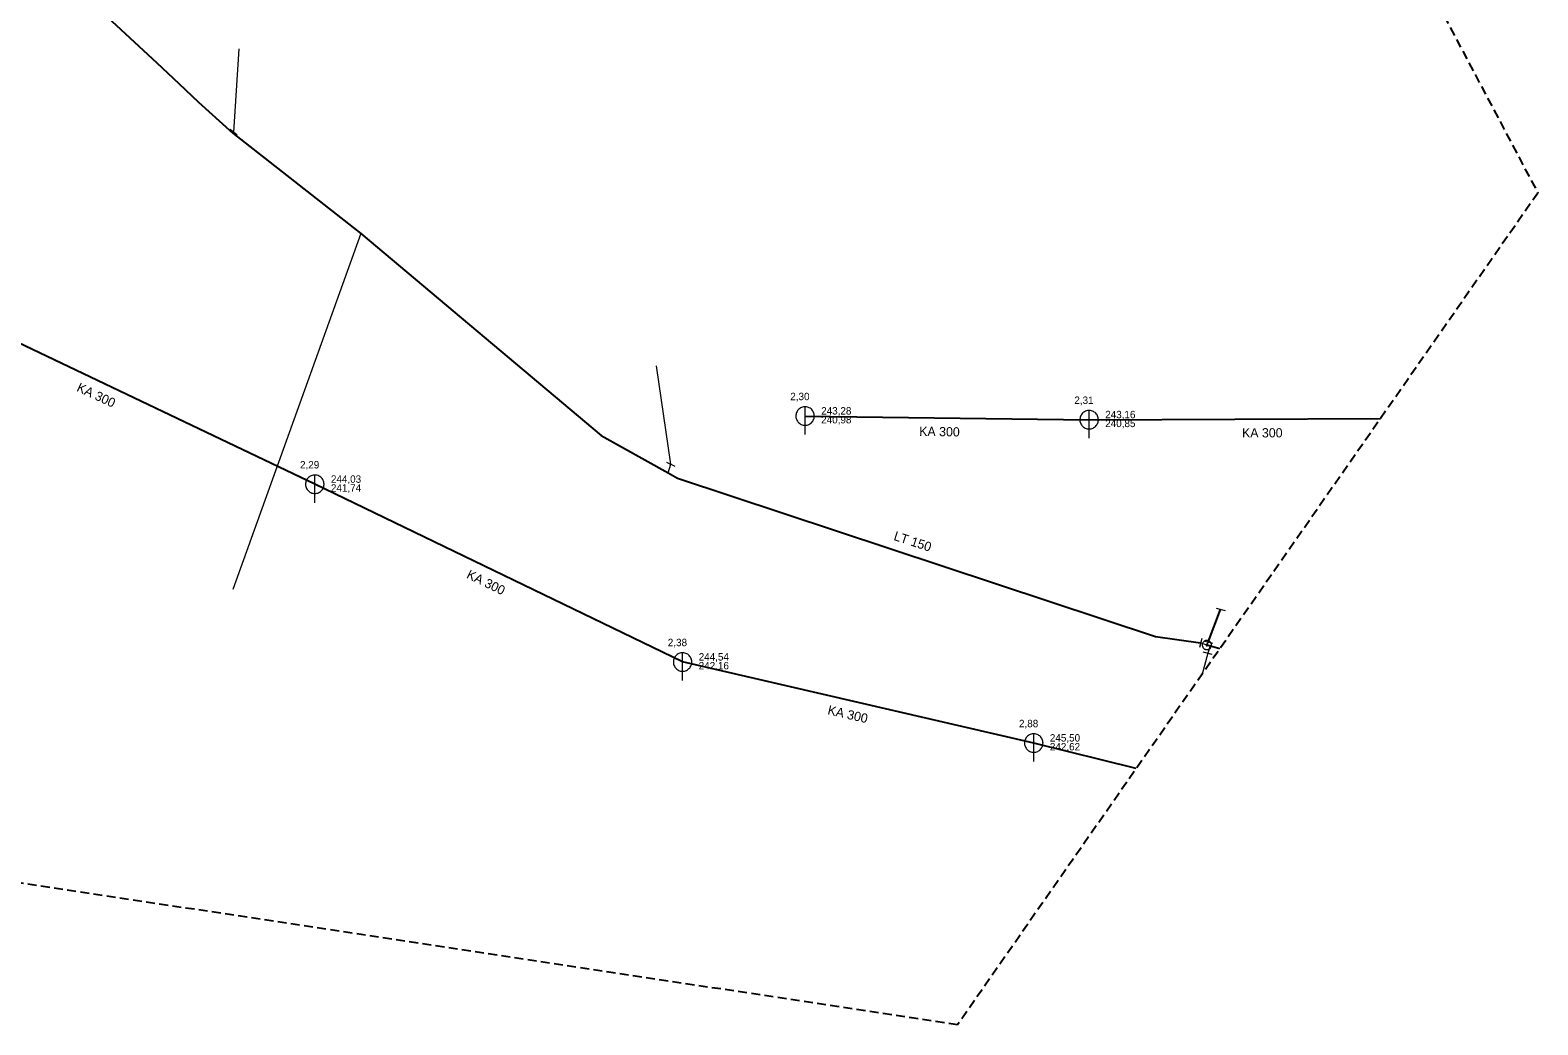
# Model space of a CAD drawing. Extents: x -777996 to -777727, y -976581 to -976199.
# Drawn here: x -777889.9 to -777726.8, y -976581.2 to -976473.6 of the extents above; entities that cross this region are included whole.
import ezdxf

# ---------------------------------------------------------------- set-up
doc = ezdxf.new("R2010")
doc.units = 0
doc.header["$LTSCALE"] = 0.32
doc.linetypes.add('MEDIUM_DASHED', pattern=[4.5, 3, -1.5])
for name, color, linetype, lineweight in [('1', 7, 'MEDIUM_DASHED', 25), ('13', 7, 'Continuous', 13), ('14', 7, 'Continuous', 25), ('17', 7, 'Continuous', 25), ('22', 7, 'Continuous', 13), ('34', 7, 'Continuous', 13), ('47', 7, 'Continuous', 13)]:
    doc.layers.add(name, color=color, linetype=linetype, lineweight=lineweight)

msp = doc.modelspace()

# ---------------------------------------------------------------- linework, layer by layer
at = {"layer": '1'}
msp.add_lwpolyline([(-777995.417, -976203.033), (-777848.18, -976198.846), (-777864.927, -976230.247), (-777726.762, -976491.225), (-777789.565, -976581.242), (-777941.686, -976558.215), (-777989.136, -976405.396)], close=True, dxfattribs=at)
at = {"layer": '13'}
for p, q in [((-777867.889, -976484.627), (-777867.309, -976475.629)), ((-777867.989, -976484.745), (-777867.889, -976484.627)), ((-777854.131, -976495.614), (-777868.002, -976534.129)), ((-777820.6, -976520.57), (-777822.127, -976509.92)), ((-777762.489, -976541.039), (-777763.1, -976543.309))]:
    msp.add_line(p, q, dxfattribs=at)
at = {"layer": '14'}
for p, q in [((-777859.114, -976522.743), (-777903.695, -976501.491)), ((-777806.059, -976515.357), (-777775.322, -976515.76)), ((-777775.322, -976515.76), (-777743.786, -976515.626)), ((-777819.315, -976541.977), (-777859.114, -976522.743)), ((-777781.311, -976550.747), (-777819.315, -976541.977)), ((-777770.223, -976553.518), (-777781.311, -976550.747))]:
    msp.add_line(p, q, dxfattribs=at)
at = {"layer": '14', "lineweight": 13}
for p, q in [((-777820.87, -976521.516), (-777820.6, -976520.57)), ((-777762.581, -976540.14), (-777763.26, -976539.92)), ((-777762.581, -976540.14), (-777762.44, -976539.829)), ((-777762.214, -976540.243), (-777762.489, -976541.039))]:
    msp.add_line(p, q, dxfattribs=at)
at = {"layer": '17'}
msp.add_line((-777762.44, -976539.829), (-777761.095, -976536.292), dxfattribs=at)
for points in [[(-777885.941, -976468.086), (-777876.204, -976477.129), (-777873.846, -976479.364), (-777871.717, -976481.385), (-777867.989, -976484.745), (-777854.131, -976495.614), (-777828.123, -976517.456), (-777820.88, -976521.51), (-777819.881, -976522.07), (-777768.129, -976539.208), (-777763.26, -976539.92)], [(-777761.165, -976540.537), (-777762.203, -976540.246), (-777762.581, -976540.14)]]:
    msp.add_lwpolyline(points, dxfattribs=at)
at = {"layer": '22'}
for p, q in [((-777806.059, -976517.357), (-777806.058, -976514.357)), ((-777775.323, -976517.76), (-777775.322, -976514.76)), ((-777859.115, -976524.744), (-777859.114, -976521.744)), ((-777819.315, -976543.977), (-777819.314, -976540.977)), ((-777781.312, -976552.747), (-777781.311, -976549.747))]:
    msp.add_line(p, q, dxfattribs=at)
for points in [[(-777805.059, -976515.357), (-777805.064, -976515.248), (-777805.082, -976515.14), (-777805.112, -976515.034), (-777805.152, -976514.933), (-777805.204, -976514.836), (-777805.266, -976514.746), (-777805.338, -976514.663), (-777805.418, -976514.589), (-777805.506, -976514.523), (-777805.6, -976514.468), (-777805.7, -976514.423), (-777805.805, -976514.39), (-777805.912, -976514.368), (-777806.021, -976514.358), (-777806.131, -976514.36), (-777806.239, -976514.374), (-777806.346, -976514.399), (-777806.449, -976514.436), (-777806.547, -976514.485), (-777806.639, -976514.543), (-777806.725, -976514.612), (-777806.802, -976514.689), (-777806.871, -976514.775), (-777806.93, -976514.867), (-777806.978, -976514.965), (-777807.015, -976515.068), (-777807.041, -976515.175), (-777807.055, -976515.283), (-777807.058, -976515.393), (-777807.048, -976515.502), (-777807.027, -976515.609), (-777806.993, -976515.713), (-777806.949, -976515.813), (-777806.894, -976515.908), (-777806.828, -976515.996), (-777806.754, -976516.076), (-777806.671, -976516.148), (-777806.581, -976516.21), (-777806.485, -976516.262), (-777806.383, -976516.303), (-777806.278, -976516.333), (-777806.17, -976516.351), (-777806.06, -976516.357), (-777805.951, -976516.351), (-777805.843, -976516.333), (-777805.738, -976516.304), (-777805.636, -976516.263), (-777805.539, -976516.211), (-777805.449, -976516.149), (-777805.366, -976516.078), (-777805.291, -976515.998), (-777805.226, -976515.91), (-777805.17, -976515.816), (-777805.126, -976515.716), (-777805.092, -976515.612), (-777805.07, -976515.504), (-777805.06, -976515.395)], [(-777774.323, -976515.76), (-777774.328, -976515.651), (-777774.346, -976515.543), (-777774.376, -976515.437), (-777774.416, -976515.336), (-777774.468, -976515.239), (-777774.53, -976515.149), (-777774.602, -976515.066), (-777774.682, -976514.992), (-777774.77, -976514.926), (-777774.864, -976514.871), (-777774.964, -976514.826), (-777775.069, -976514.793), (-777775.176, -976514.771), (-777775.285, -976514.761), (-777775.395, -976514.763), (-777775.503, -976514.777), (-777775.61, -976514.802), (-777775.713, -976514.839), (-777775.811, -976514.888), (-777775.903, -976514.946), (-777775.989, -976515.015), (-777776.066, -976515.092), (-777776.135, -976515.178), (-777776.194, -976515.27), (-777776.242, -976515.368), (-777776.279, -976515.471), (-777776.305, -976515.578), (-777776.319, -976515.686), (-777776.322, -976515.796), (-777776.312, -976515.905), (-777776.291, -976516.012), (-777776.257, -976516.116), (-777776.213, -976516.216), (-777776.158, -976516.311), (-777776.092, -976516.399), (-777776.018, -976516.479), (-777775.935, -976516.551), (-777775.845, -976516.613), (-777775.749, -976516.665), (-777775.647, -976516.706), (-777775.542, -976516.736), (-777775.434, -976516.754), (-777775.324, -976516.76), (-777775.215, -976516.754), (-777775.107, -976516.736), (-777775.002, -976516.707), (-777774.9, -976516.666), (-777774.803, -976516.614), (-777774.713, -976516.552), (-777774.63, -976516.481), (-777774.555, -976516.401), (-777774.49, -976516.313), (-777774.434, -976516.219), (-777774.39, -976516.119), (-777774.356, -976516.015), (-777774.334, -976515.907), (-777774.324, -976515.798)], [(-777858.115, -976522.744), (-777858.12, -976522.635), (-777858.138, -976522.527), (-777858.168, -976522.421), (-777858.208, -976522.32), (-777858.26, -976522.223), (-777858.322, -976522.133), (-777858.394, -976522.05), (-777858.474, -976521.976), (-777858.562, -976521.91), (-777858.656, -976521.855), (-777858.756, -976521.81), (-777858.861, -976521.777), (-777858.968, -976521.755), (-777859.077, -976521.745), (-777859.187, -976521.747), (-777859.295, -976521.761), (-777859.402, -976521.786), (-777859.505, -976521.823), (-777859.603, -976521.872), (-777859.695, -976521.93), (-777859.781, -976521.999), (-777859.858, -976522.076), (-777859.927, -976522.162), (-777859.986, -976522.254), (-777860.034, -976522.352), (-777860.071, -976522.455), (-777860.097, -976522.562), (-777860.111, -976522.67), (-777860.114, -976522.78), (-777860.104, -976522.889), (-777860.083, -976522.996), (-777860.049, -976523.1), (-777860.005, -976523.2), (-777859.95, -976523.295), (-777859.884, -976523.383), (-777859.81, -976523.463), (-777859.727, -976523.535), (-777859.637, -976523.597), (-777859.541, -976523.649), (-777859.439, -976523.69), (-777859.334, -976523.72), (-777859.226, -976523.738), (-777859.116, -976523.744), (-777859.007, -976523.738), (-777858.899, -976523.72), (-777858.794, -976523.691), (-777858.692, -976523.65), (-777858.595, -976523.598), (-777858.505, -976523.536), (-777858.422, -976523.465), (-777858.347, -976523.385), (-777858.282, -976523.297), (-777858.226, -976523.203), (-777858.182, -976523.103), (-777858.148, -976522.999), (-777858.126, -976522.891), (-777858.116, -976522.782)], [(-777818.315, -976541.977), (-777818.32, -976541.868), (-777818.338, -976541.76), (-777818.368, -976541.654), (-777818.408, -976541.553), (-777818.46, -976541.456), (-777818.522, -976541.366), (-777818.594, -976541.283), (-777818.674, -976541.209), (-777818.762, -976541.143), (-777818.856, -976541.088), (-777818.956, -976541.043), (-777819.061, -976541.01), (-777819.168, -976540.988), (-777819.277, -976540.978), (-777819.387, -976540.98), (-777819.495, -976540.994), (-777819.602, -976541.019), (-777819.705, -976541.056), (-777819.803, -976541.105), (-777819.895, -976541.163), (-777819.981, -976541.232), (-777820.058, -976541.309), (-777820.127, -976541.395), (-777820.186, -976541.487), (-777820.234, -976541.585), (-777820.271, -976541.688), (-777820.297, -976541.795), (-777820.311, -976541.903), (-777820.314, -976542.013), (-777820.304, -976542.122), (-777820.283, -976542.229), (-777820.249, -976542.333), (-777820.205, -976542.433), (-777820.15, -976542.528), (-777820.084, -976542.616), (-777820.01, -976542.696), (-777819.927, -976542.768), (-777819.837, -976542.83), (-777819.741, -976542.882), (-777819.639, -976542.923), (-777819.534, -976542.953), (-777819.426, -976542.971), (-777819.316, -976542.977), (-777819.207, -976542.971), (-777819.099, -976542.953), (-777818.994, -976542.924), (-777818.892, -976542.883), (-777818.795, -976542.831), (-777818.705, -976542.769), (-777818.622, -976542.698), (-777818.547, -976542.618), (-777818.482, -976542.53), (-777818.426, -976542.436), (-777818.382, -976542.336), (-777818.348, -976542.232), (-777818.326, -976542.124), (-777818.316, -976542.015)], [(-777780.312, -976550.747), (-777780.317, -976550.638), (-777780.335, -976550.53), (-777780.365, -976550.424), (-777780.405, -976550.323), (-777780.457, -976550.226), (-777780.519, -976550.136), (-777780.591, -976550.053), (-777780.671, -976549.979), (-777780.759, -976549.913), (-777780.853, -976549.858), (-777780.953, -976549.813), (-777781.058, -976549.78), (-777781.165, -976549.758), (-777781.274, -976549.748), (-777781.384, -976549.75), (-777781.492, -976549.764), (-777781.599, -976549.789), (-777781.702, -976549.826), (-777781.8, -976549.875), (-777781.892, -976549.933), (-777781.978, -976550.002), (-777782.055, -976550.079), (-777782.124, -976550.165), (-777782.183, -976550.257), (-777782.231, -976550.355), (-777782.268, -976550.458), (-777782.294, -976550.565), (-777782.308, -976550.673), (-777782.311, -976550.783), (-777782.301, -976550.892), (-777782.28, -976550.999), (-777782.246, -976551.103), (-777782.202, -976551.203), (-777782.147, -976551.298), (-777782.081, -976551.386), (-777782.007, -976551.466), (-777781.924, -976551.538), (-777781.834, -976551.6), (-777781.738, -976551.652), (-777781.636, -976551.693), (-777781.531, -976551.723), (-777781.423, -976551.741), (-777781.313, -976551.747), (-777781.204, -976551.741), (-777781.096, -976551.723), (-777780.991, -976551.694), (-777780.889, -976551.653), (-777780.792, -976551.601), (-777780.702, -976551.539), (-777780.619, -976551.468), (-777780.544, -976551.388), (-777780.479, -976551.3), (-777780.423, -976551.206), (-777780.379, -976551.106), (-777780.345, -976551.002), (-777780.323, -976550.894), (-777780.313, -976550.785)]]:
    msp.add_lwpolyline(points, close=True, dxfattribs=at)
at = {"layer": '34'}
for p, q in [((-777868.272, -976484.306), (-777867.506, -976484.948)), ((-777821.049, -976520.351), (-777820.15, -976520.789)), ((-777761.579, -976536.167), (-777760.61, -976536.417)), ((-777763.134, -976539.435), (-777763.384, -976540.404)), ((-777762.006, -976541.168), (-777762.971, -976540.908)), ((-777762.924, -976539.704), (-777761.955, -976539.954))]:
    msp.add_line(p, q, dxfattribs=at)
at = {"layer": '47'}
for points in [[(-777762.089, -976540.233), (-777762.083, -976540.181), (-777762.081, -976540.129), (-777762.085, -976540.077), (-777762.094, -976540.025), (-777762.108, -976539.975), (-777762.129, -976539.926), (-777762.154, -976539.881), (-777762.183, -976539.837), (-777762.216, -976539.797), (-777762.254, -976539.761), (-777762.296, -976539.728), (-777762.341, -976539.702), (-777762.387, -976539.678), (-777762.437, -976539.661), (-777762.487, -976539.648), (-777762.539, -976539.642), (-777762.591, -976539.64), (-777762.644, -976539.644), (-777762.695, -976539.653), (-777762.745, -976539.667), (-777762.794, -976539.688), (-777762.84, -976539.713), (-777762.884, -976539.742), (-777762.924, -976539.775), (-777762.959, -976539.813), (-777762.992, -976539.855), (-777763.019, -976539.899), (-777763.042, -976539.946), (-777763.059, -976539.996), (-777763.072, -976540.046), (-777763.078, -976540.098), (-777763.08, -976540.15), (-777763.077, -976540.203), (-777763.067, -976540.254), (-777763.053, -976540.304), (-777763.033, -976540.353), (-777763.008, -976540.399), (-777762.979, -976540.442), (-777762.945, -976540.483), (-777762.907, -976540.518), (-777762.865, -976540.551), (-777762.822, -976540.578), (-777762.774, -976540.601), (-777762.724, -976540.618), (-777762.674, -976540.631), (-777762.622, -976540.637), (-777762.57, -976540.639), (-777762.518, -976540.636), (-777762.466, -976540.626), (-777762.416, -976540.612), (-777762.367, -976540.592), (-777762.322, -976540.567), (-777762.278, -976540.538), (-777762.238, -976540.504), (-777762.202, -976540.466), (-777762.169, -976540.424), (-777762.143, -976540.38), (-777762.119, -976540.333), (-777762.102, -976540.283)], [(-777762.5, -976540.155), (-777762.498, -976540.146), (-777762.499, -976540.138), (-777762.499, -976540.129), (-777762.501, -976540.121), (-777762.503, -976540.112), (-777762.507, -976540.105), (-777762.51, -976540.097), (-777762.515, -976540.09), (-777762.521, -976540.084), (-777762.527, -976540.077), (-777762.534, -976540.072), (-777762.541, -976540.068), (-777762.549, -976540.064), (-777762.556, -976540.061), (-777762.565, -976540.059), (-777762.574, -976540.057), (-777762.582, -976540.058), (-777762.591, -976540.058), (-777762.599, -976540.06), (-777762.608, -976540.062), (-777762.615, -976540.066), (-777762.623, -976540.069), (-777762.63, -976540.074), (-777762.637, -976540.08), (-777762.643, -976540.086), (-777762.648, -976540.093), (-777762.652, -976540.1), (-777762.656, -976540.108), (-777762.659, -976540.115), (-777762.661, -976540.124), (-777762.663, -976540.133), (-777762.662, -976540.141), (-777762.662, -976540.15), (-777762.66, -976540.158), (-777762.658, -976540.167), (-777762.655, -976540.174), (-777762.651, -976540.182), (-777762.646, -976540.189), (-777762.64, -976540.196), (-777762.634, -976540.202), (-777762.627, -976540.207), (-777762.62, -976540.211), (-777762.612, -976540.215), (-777762.605, -976540.218), (-777762.596, -976540.22), (-777762.587, -976540.222), (-777762.579, -976540.221), (-777762.57, -976540.221), (-777762.562, -976540.219), (-777762.553, -976540.217), (-777762.546, -976540.214), (-777762.538, -976540.21), (-777762.531, -976540.205), (-777762.525, -976540.199), (-777762.518, -976540.193), (-777762.513, -976540.186), (-777762.509, -976540.179), (-777762.505, -976540.171), (-777762.502, -976540.164)]]:
    msp.add_lwpolyline(points, close=True, dxfattribs=at)

# ---------------------------------------------------------------- texts
at = {"layer": '1'}
for s, rotation, p in [('KA 300', 335, (-777884.967, -976512.618)), ('KA 300', 359, (-777793.716, -976517.503)), ('LT 150', 342, (-777796.544, -976528.76)), ('KA 300', 334, (-777842.779, -976532.841)), ('KA 300', 347, (-777803.682, -976547.621))]:
    msp.add_text(s, height=1, rotation=rotation, dxfattribs=at).set_placement(p)
for s, height, p in [('2,30', 0.8, (-777807.659, -976513.645)), ('2,31', 0.8, (-777776.922, -976514.048)), ('KA 300', 1, (-777758.775, -976517.674)), ('2,29', 0.8, (-777860.714, -976521.032)), ('2,38', 0.8, (-777820.914, -976540.265)), ('2,88', 0.8, (-777782.911, -976549.035))]:
    msp.add_text(s, height=height, dxfattribs=at).set_placement(p)
at = {"layer": '22'}
for s, p in [('243,28', (-777804.316, -976515.196)), ('243,16', (-777773.58, -976515.599)), ('240,98', (-777804.316, -976516.156)), ('240,85', (-777773.58, -976516.559)), ('244,03', (-777857.372, -976522.584)), ('241,74', (-777857.372, -976523.544)), ('244,54', (-777817.572, -976541.817)), ('242,16', (-777817.572, -976542.777)), ('245,50', (-777779.569, -976550.586)), ('242,62', (-777779.569, -976551.546))]:
    msp.add_text(s, height=0.8, dxfattribs=at).set_placement(p)

doc.saveas('drawing.dxf')
